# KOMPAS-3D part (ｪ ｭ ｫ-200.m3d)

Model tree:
1. Эскиз:1
2. Операция выдавливания:1
     Расстояние 1 = 1
3. Эскиз:2
4. Операция выдавливания:2
     Расстояние 1 = 2
5. Эскиз:3
6. Вырезать элемент выдавливания:1
     Расстояние 1 = 200
7. Эскиз:4
8. Операция выдавливания:3
     Расстояние 1 = 5
9. Эскиз:5
10. Операция выдавливания:4
     Расстояние 1 = 1
11. Эскиз:6
12. Операция выдавливания:5
     Расстояние 1 = 9
13. Эскиз:7
14. Операция выдавливания:6
     Расстояние 1 = 9; Расстояние 2 = 200
